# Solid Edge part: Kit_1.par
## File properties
Sűrűség: 0,000 kg/m^3
Pontosság: 0,990
Author: ahadarics
Last saved by: psaghy
Revision: 78
Username: ahadarics
Dokumentum tartalom típus: 0
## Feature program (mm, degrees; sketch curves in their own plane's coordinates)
base feature "unnamed BaseFeature 1"
sketch for "Furat_1" plane through (0, 0, 50) normal (0, 0, 1) x-axis (-1, 0, 0)
  hole centre (-70, 70) bore radius 6.9175
hole "Furat_1" nominal diameter 16 finite  ThreadDepth = 24 mm
sketch for "unnamed Hole 1" plane through (0, 0, 50) normal (0, 0, 1) x-axis (-1, 0, 0)
  hole centre (-70, -70) bore radius 6.9175
hole "unnamed Hole 1" finite
sketch for "unnamed Hole 2" plane through (0, 0, 50) normal (0, 0, 1) x-axis (-1, 0, 0)
  hole centre (70, -70) bore radius 6.9175
hole "unnamed Hole 2" finite
sketch for "unnamed Hole 3" plane through (0, 0, 50) normal (0, 0, 1) x-axis (-1, 0, 0)
  hole centre (70, 70) bore radius 6.9175
hole "unnamed Hole 3" finite
pattern "unnamed Pattern 1" of "Furat_1", "unnamed Hole 1", "unnamed Hole 2", "unnamed Hole 3"
sketch for "Furat_5" plane through (15.0012, -89, 24.5) normal (0, -1, 0) x-axis (0, 0, -1)
  hole centre (0, -0.0012) bore radius 12.0585
hole "Furat_5" nominal diameter 26.441 finite  ThreadDepth = 26.5 mm
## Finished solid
Body 1: solid body, 625 faces, 1531 edges, 959 vertices, 3 internal voids.
  Faces by surface: cylinder 205, plane 191, torus 124, cone 41, spline 41, swept 19, sphere 4
  Edges by curve: circle 567, line 546, curve on surface 342, spline 58, intersection 16, ellipse 2
Bounding box of the edges (mm; curved faces can reach further): 180.000 x 180.000 x 105.000, from (-90, -90, 0) to (90, 90, 105).
Cylindrical faces by radius (mm): R0.4 x1, R0.4595 x1, R0.4687 x1, R0.4912 x1, R0.5 x2, R0.5036 x1, R0.5393 x1, R0.5619 x1, R0.5738 x1, R0.5925 x1, R0.6033 x1, R0.6109 x1, R0.6502 x1, R0.6626 x1, R0.6941 x1, R0.7492 x1, R0.7991 x1, R0.8155 x1, R0.8225 x1, R0.8523 x1, R0.8677 x1, R0.9066 x1, R0.9072 x1, R0.9188 x1, R0.9543 x1, R0.9562 x1, R1 x56, R1.0083 x12, R1.0187 x1, R1.0708 x1, R1.1067 x1, R1.3671 x1, R1.5039 x1, R1.5591 x1, R1.5808 x1, R1.6101 x1, R1.6481 x1, R1.7807 x1, R1.8842 x1, R1.9083 x2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
Conical faces (half-angle, radius in mm at the cone's reference point): 1.6538 deg R21.75 x1, 3.5477 deg R22.7454 x1, 5.1705 deg R20.4 x1, 8.3742 deg R20.0032 x1, 13.2989 deg R21.1846 x1, 14.7738 deg R20.7787 x1, 25.0169 deg R24.31 x1, 30 deg R22.3557 x2, 30 deg R22.7887 x1, 45 deg R3.85 x1, 45 deg R4.25 x1, 45 deg R6.91 x12, 45 deg R8.9 x8, 45 deg R12.055 x1, 45 deg R18.75 x4, 45 deg R20.15 x2, 45 deg R25.35 x1, 45 deg R31.75 x1
Toroidal faces (ring radius, tube radius in mm): R1 r1 x14, R2 r1 x9, R2.0237 r1.0014 x6, R2.0238 r1.0015 x4, R3 r1 x29, R4 r1 x8, R5.85 r0.2 x1, R11 r1 x1, R12 r0.5 x12, R13.8 r0.8 x4, R15 r2 x1, R15.5 r0.5 x1, R18 r1 x5, R19 r1 x4, R20 r1 x12, R20.3 r0.3 x1, R20.3088 r0.3 x1, R21.4279 r0.25 x1, R22.2464 r0.5 x1, R24.8 r0.2 x1, R30 r1 x1, R34.25 r1 x7
Spherical faces by radius (mm): R1 x4
Planar faces by outward normal: +x 14, +y 5, +z 58, -x 15, -y 29, -z 16, oblique 54
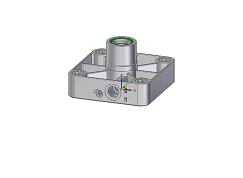
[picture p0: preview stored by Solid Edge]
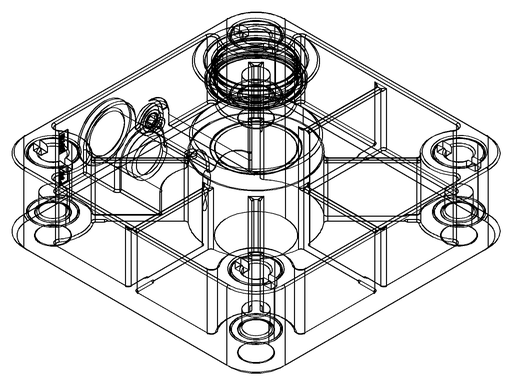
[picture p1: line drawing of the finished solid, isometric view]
